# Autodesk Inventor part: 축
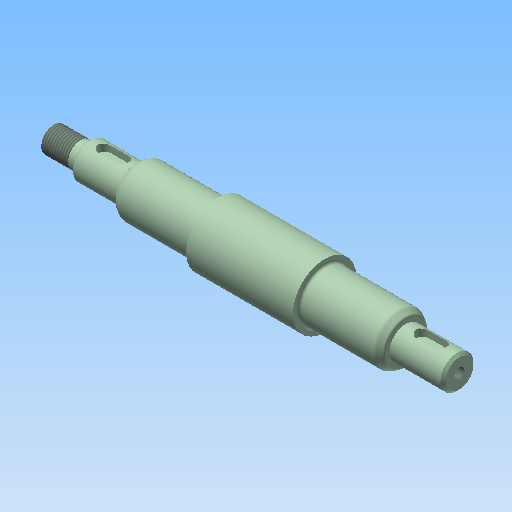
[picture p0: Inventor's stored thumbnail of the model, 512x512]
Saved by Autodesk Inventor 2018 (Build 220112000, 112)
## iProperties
Created: 2024-02
Part Number: 축
Material: 강철, 탄소
Document SubType Name: Modeling
Designer: mdu-01
Density: 1 g/cm^3
Appearance: 기본값(1)
Author: mdu-01
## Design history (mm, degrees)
sketch "스케치1"
  geometry: L1 (0, 0)-(160, 0); L2 (0, 0)-(0, -5); L3 (0, -5)-(14, -5); L4 (14, -5)-(14, -6); L5 (15, -7)-(33, -7); L6 (33, -7)-(33, -7.923); L7 (36.134, -10)-(64, -10); L8 (65, -11)-(65, -12.5); L9 (65, -12.5)-(107, -12.5); L10 (107, -12.5)-(107, -11); L11 (108, -10)-(135.866, -10); L12 (139, -7.923)-(139, -6.5); L13 (139, -6.5)-(159, -6.5); L14 (160, -5.5)-(160, 0); L15 (159, -6.5)-(160, -5.5); L16 (14, -6)-(15, -7); L17 (33.5, -8.789)-(35.134, -9.732); L18 (138.5, -8.789)-(136.866, -9.732); L19 (18, 7)-(30, 7); L20 (30, 7)-(30, 4); L21 (30, 4)-(18, 4); L22 (18, 4)-(18, 7); L23 (143, 6.5)-(155, 6.5); L24 (155, 6.5)-(155, 3.5); L25 (155, 3.5)-(143, 3.5); L26 (143, 3.5)-(143, 6.5); A1 r 1 centre (64, -11) between (65, -11) and (64, -10); A2 r 1 centre (108, -11) between (108, -10) and (107, -11); A3 r 1 centre (34, -7.923) between (33, -7.923) and (33.5, -8.789); A4 r 1 centre (138, -7.923) between (138.5, -8.789) and (139, -7.923); A5 r 2 centre (135.866, -8) between (135.866, -10) and (136.866, -9.732); A6 r 2 centre (36.134, -8) between (35.134, -9.732) and (36.134, -10); 4 further points
  constraints: 52 end point, 15 parallel, 12 point on circle, 12 tangent, 8 point on line, 6 centre point, 4 perpendicular, 3 equal radius, 3 horizontal, 1 collinear
  dimensions: "d0" = 160 distance of L1.start L1.end; "d1" = 14 distance between parallel lines of L4 L2; "d2" = 33 distance between parallel lines of L6 L2; "d3" = 65 distance between parallel lines of L8 L2; "d4" = 21 distance between parallel lines of L12 L14; "d5" = 53 distance between parallel lines of L10 L14; "d6" = 10 diameter of L3 L1; "d7" = 14 diameter of L5 L1; "d8" = 20 diameter of L7 L1; "d9" = 13 diameter of L13 L1; "d10" = 25 diameter of L9 L1; "d11" = 1 radius of A1; "d12" = 1 distance of L13.end point (160, -6.5); "d13" = 1 distance of L14.start point (160, -6.5) (= d12); "d14" = 1 distance of L4.end point (14, -7) (= d12); "d15" = 1 distance of L5.start point (14, -7) (= d14); "d16" = 17 diameter of point (139, -8.5) L1; "d17" = 30 deg angle of L11 L18; "d18" = 17 diameter of point (33, -8.5) L1; "d19" = 30 deg angle of L7 L17; "d20" = 1 radius of A3; "d21" = 2 radius of A5; "d22" = 3 distance between parallel lines of L21 L19; "d23" = 12 distance between parallel lines of L20 L22; "d24" = 3 distance between parallel lines of L20 L6; "d25" = 14 diameter of L19 L1; "d26" = 3 distance between parallel lines of L25 L23; "d27" = 12 distance between parallel lines of L24 L26; "d28" = 4 distance between parallel lines of L26 L12; "d29" = 13 diameter of L23 L1
revolve "회전1" stored, may be unused: angle "d30" = 90 deg
extrude "돌출1" cut sketch "스케치1" stored distance "d31" = 5; taper "d32" = 0 deg
fillet "모깎기1" dims "d33" = 2.5
feature "스레드1" dims "d34" = 11, "d35" = 0
chamfer "모따기1" distance "d36" = 0.541; stored, may be unused: second distance "d37" = 2, angle "d38" = 45 deg
hole "구멍1" diameter "d41" = 4.134; stored, may be unused: countersink angle "d45" = 90 deg, drill point angle "d47" = 118 deg; dims "d39" = 10, "d40" = 10, "d42" = 10, "d43" = 4, "d44" = 2, "d46" = 12
node "솔리드1"
